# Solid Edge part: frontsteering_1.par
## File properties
Author: KULL
Template: Iso Metric Part.par
Last saved by: KULL
Revision: 26
Application: Solid Edge
Accuracy: 0,990
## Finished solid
Body 1: solid body, 239 faces, 533 edges, 296 vertices.
  Faces by surface: cylinder 104, torus 63, plane 40, blend 27, sphere 5
  Edges by curve: circle 280, line 198, ellipse 28, intersection 26, curve on surface 1
Bounding box of the edges (mm; curved faces can reach further): 28.000 x 37.345 x 39.295, from (-5, -15.242, -19.6474) to (23, 22.1032, 19.6474).
Cylindrical faces by radius (mm): R0.2 x28, R0.8 x37, R1.3 x1, R1.8 x2, R2 x4, R3 x5, R4 x12, R5 x8, R6 x3, R8 x2, R9 x2
Toroidal faces (ring radius, tube radius in mm): R1 r0.2 x2, R1 r0.8 x2, R1.2 r0.8 x2, R1.5 r0.2 x2, R1.6 r0.2 x2, R1.7 r0.4 x1, R2.2 r0.8 x4, R2.4 r0.4 x2, R3.2 r0.2 x4, R3.2 r0.8 x2, R4.2 r0.2 x12, R4.2 r0.8 x4, R4.8 r0.2 x4, R4.8 r0.8 x4, R5.2 r0.8 x4, R5.8 r0.8 x4, R8.2 r0.2 x2, R8.8 r0.2 x2, R8.8 r0.8 x2, R9.8 r0.8 x2
Spherical faces by radius (mm): R0.8 x2, R3 x1, R4 x2
Planar faces by outward normal: +x 3, +y 5, +z 2, -x 4, -y 5, -z 2, oblique 19
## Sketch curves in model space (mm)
line (0, 0, 23) -> (0, 0, 11.1472)
line (-5.2801, 22, 0) -> (0.8486, 18.7374, 0)
circle centre (0, 0, -23) radius 4
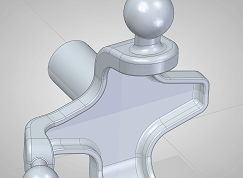
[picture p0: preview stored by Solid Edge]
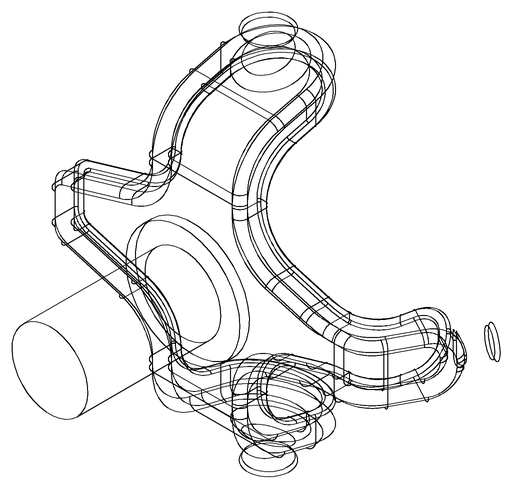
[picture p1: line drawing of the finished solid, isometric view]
